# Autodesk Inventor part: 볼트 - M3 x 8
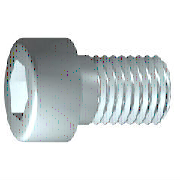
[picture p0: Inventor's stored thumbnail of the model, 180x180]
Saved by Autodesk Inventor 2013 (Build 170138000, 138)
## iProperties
IsCustomPart: 0
Created: 2012-02
Part Number: 볼트 - M3 x 8
Material: 스테인리스강
Description: 6각 소켓 머리 캡 나사
Document SubType Name: Modeling
Standard: ISO 4762
Designer: mduedu
Standard Revision: Fourth edition 2004-03-01
Standards Organization: ISO
Language: ko-KR
Size Designation: M3 x 8
Categories: <MemberInstance><Categories><Category DisplayName="조임쇠" InternalName="e4da775c-781d-43d5-af7c-5136215cf5a6" Mnemonic="FSTN"><Category DisplayName="볼트" InternalN
Density: 7.75 g/cm^3
Author: mduedu
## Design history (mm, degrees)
sketch "스케치1"
  geometry: L1 (-0.867, 0)-(8, 0); L2 (8, 0)-(8, 1.5); L3 (8, 1.5)-(1.25, 1.5); L4 (1.25, 1.5)-(0.943, 1.5); L5 (0.943, 1.5)-(0, 1.5); L6 (0, 1.5)-(0, 2.75); L7 (0, 2.75)-(-3, 2.75); L8 (-3, 2.75)-(-3, 1.443); L9 (-3, 1.443)-(-1.7, 1.443); L10 (-1.7, 1.443)-(-0.867, 0); L11 (-5.2, 0)-(10.2, 0) reference; L12 (0, -0.55)-(0, 3.3) reference; L13 (1.25, 1.5)-(0, 1.5)
  constraints: 22 end point, 6 parallel, 2 collinear, 2 perpendicular, 1 horizontal, 1 point on line
  dimensions: "d1" = 6.75 distance from line of L3.end L2 (= GEL); "d2" = 0.30683 distance of L4.end L3.end (computed from GAL); "d3" = 3 distance between parallel lines of L8 L6 (= KOH); "d4" = 1.3 distance of L8.end L9.end (= INTI); "d5" = 60 deg angle of L10 L1; "d6" = 3 diameter of L3 L1 (= GD); "d7" = 3 diameter of L5 L1 (= BDM); "d8" = 2.88675 diameter of L9 L1 (= 1.1547 x SW); "d9" = 5.5 diameter of L7 L1 (= KOD); "d26" = 8 distance between parallel lines of L12 L2 (= NLG)
revolve "본체" sketch "스케치1" stored, may be unused: angle "d10" = 90 deg
sketch "스케치2"
  geometry: L1 (0, -3.85)-(0, 3.85) reference; L2 (-3.85, 0)-(3.85, 0) reference; L3 (1.443, 0)-(0.722, -1.25); L4 (0.722, -1.25)-(-0.722, -1.25); L5 (-0.722, -1.25)-(-1.443, 0); L6 (-1.443, 0)-(-0.722, 1.25); L7 (-0.722, 1.25)-(0.722, 1.25); L8 (0.722, 1.25)-(1.443, 0); 2 further points
  constraints: 12 end point, 1 coincident, 1 horizontal alignment, 1 point on line, 12 other
extrude "슬롯" join sketch "스케치2" stored distance "d11" = 10; taper "d12" = 0 deg
workplane "Work Plane1"
fillet "Fillet2" dims "d30" = 0.1 (= R)
body "Solid1"
fillet "모깎기1" dims "d17" = 0.3 (= RR)
feature "스레드" dims "d13" = 6.75 (= GEL), "d14" = 0
chamfer "모따기1" distance "d15" = 0.30673 (= -0.5 x SPD + 0.5 x GD); stored, may be unused: second distance "d16" = 0.30673 (= GUL), angle "d27" = 45 deg
other parameters: "GD" = 3 [user parameter; used in 2 equation terms], "NLG" = 8 [user parameter; used in 1 equation term], "GEL" = 6.75 [user parameter; used in 2 equation terms], "KOD" = 5.5 [user parameter; used in 1 equation term], "KOH" = 3 [user parameter; used in 1 equation term], "INTI" = 1.3 [user parameter; used in 1 equation term], "GAL" = 0.30673 (= 0.61345 x PTC) [user parameter; used in 1 equation term], "GUL" = 0.30673 (= 0.61345 x PTC) [user parameter; used in 1 equation term], "BDM" = 3 (= NND) [user parameter; used in 1 equation term], "SW" = 2.5 [user parameter; used in 2 equation terms], "RR" = 0.3 [user parameter; used in 1 equation term], "SPD" = 2.38655 (= NND - 1.2269 x PTC) [user parameter; used in 1 equation term], "d19" = 0, "d28" = 0, "d29" = 0, "R" = 0.1 [user parameter; used in 1 equation term], "TOA" = 30 deg [user parameter], "GD1" = 2.38655 (= THREADDIA - 1.2269 x PTC) [user parameter], "THREADDIA" = 3 [user parameter; used in 1 equation term], "FAWI" = 45 deg [user parameter], "PTC" = 0.5 [user parameter; used in 5 equation terms], "NND" = 3 [user parameter; used in 2 equation terms], "E0" = 2.8875 (= 1.155 x SW) [user parameter]
